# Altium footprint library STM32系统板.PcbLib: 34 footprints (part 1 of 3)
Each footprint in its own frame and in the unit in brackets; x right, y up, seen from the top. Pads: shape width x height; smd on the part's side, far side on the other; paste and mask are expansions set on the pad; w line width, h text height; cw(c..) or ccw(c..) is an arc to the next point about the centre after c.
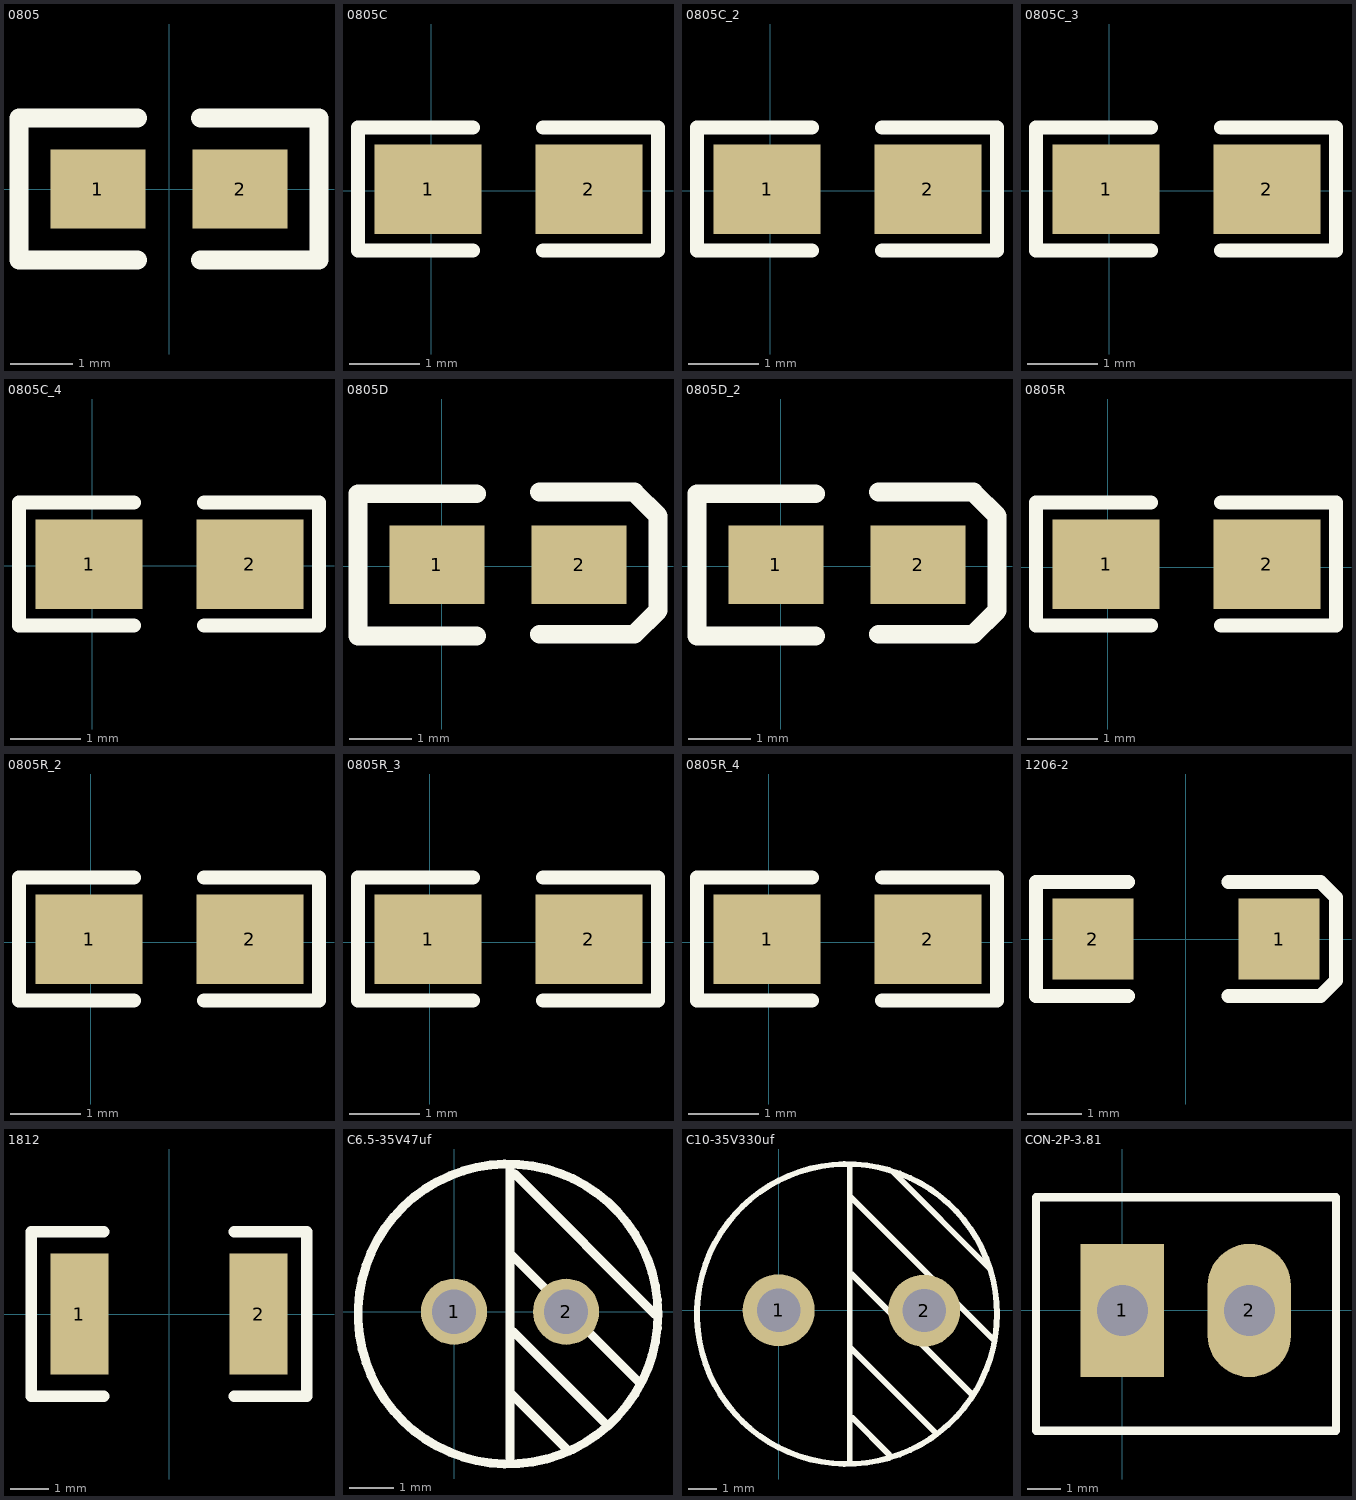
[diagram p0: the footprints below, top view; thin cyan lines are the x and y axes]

## 0805 [mil]
pads (2):
  rect 60x50 smd: 1(-45,0) 2(45,0)
Top Overlay:
  lines w12: -20,-45 -95,-45 -95,45 -20,45 ; 20,-45 95,-45 95,45 20,45

## 0805C [mil]
pads (2):
  rect 60x50 smd: 1(-1.89,0.71) 2(88.11,0.71)
Top Overlay:
  lines w7.87: 23.15,-33.54 -41.02,-33.54 -41.02,35.35 23.15,35.35 ; 62.52,-33.54 126.69,-33.54 126.69,35.35 62.52,35.35

## 0805C_2 [mil]
pads (2):
  rect 60x50 smd: 1(-1.89,0.71) 2(88.11,0.71)
Top Overlay:
  lines w7.87: 23.15,-33.54 -41.02,-33.54 -41.02,35.35 23.15,35.35 ; 62.52,-33.54 126.69,-33.54 126.69,35.35 62.52,35.35

## 0805C_3 [mil]
pads (2):
  rect 60x50 smd: 1(-1.89,0.71) 2(88.11,0.71)
Top Overlay:
  lines w7.87: 23.15,-33.54 -41.02,-33.54 -41.02,35.35 23.15,35.35 ; 62.52,-33.54 126.69,-33.54 126.69,35.35 62.52,35.35

## 0805C_4 [mil]
pads (2):
  rect 60x50 smd: 1(-1.89,0.71) 2(88.11,0.71)
Top Overlay:
  lines w7.87: 23.15,-33.54 -41.02,-33.54 -41.02,35.35 23.15,35.35 ; 62.52,-33.54 126.69,-33.54 126.69,35.35 62.52,35.35

## 0805D [mil]
pads (2):
  rect 60x50 smd: 1(-3.11,0.94) 2(86.89,0.94)
Top Overlay:
  lines w12: 21.89,-44.06 -53.11,-44.06 -53.11,45.94 21.89,45.94 ; 61.89,-43.07 121.89,-43.07 136.89,-28.07 136.89,31.93 121.89,46.93 61.89,46.93

## 0805D_2 [mil]
pads (2):
  rect 60x50 smd: 1(-3.11,0.94) 2(86.89,0.94)
Top Overlay:
  lines w12: 21.89,-44.06 -53.11,-44.06 -53.11,45.94 21.89,45.94 ; 61.89,-43.07 121.89,-43.07 136.89,-28.07 136.89,31.93 121.89,46.93 61.89,46.93

## 0805R [mil]
pads (2):
  rect 60x50 smd: 1(-0.91,1.69) 2(89.09,1.69)
Top Overlay:
  lines w7.87: 24.13,-32.56 -40.04,-32.56 -40.04,36.34 24.13,36.34 ; 63.5,-32.56 127.68,-32.56 127.68,36.34 63.5,36.34

## 0805R_2 [mil]
pads (2):
  rect 60x50 smd: 1(-0.91,1.69) 2(89.09,1.69)
Top Overlay:
  lines w7.87: 24.13,-32.56 -40.04,-32.56 -40.04,36.34 24.13,36.34 ; 63.5,-32.56 127.68,-32.56 127.68,36.34 63.5,36.34

## 0805R_3 [mil]
pads (2):
  rect 60x50 smd: 1(-0.91,1.69) 2(89.09,1.69)
Top Overlay:
  lines w7.87: 24.13,-32.56 -40.04,-32.56 -40.04,36.34 24.13,36.34 ; 63.5,-32.56 127.68,-32.56 127.68,36.34 63.5,36.34

## 0805R_4 [mil]
pads (2):
  rect 60x50 smd: 1(-0.91,1.69) 2(89.09,1.69)
Top Overlay:
  lines w7.87: 24.13,-32.56 -40.04,-32.56 -40.04,36.34 24.13,36.34 ; 63.5,-32.56 127.68,-32.56 127.68,36.34 63.5,36.34

## 1206-2 [mm]
pads (2):
  rect 1.5x1.5 smd: 1(1.714,0) 2(-1.714,0)
Top Overlay:
  lines w0.254: -1.064,-1.05 -2.764,-1.05 -2.764,0 -2.764,1.05 -1.064,1.05 ; 0.78,-1.05 2.48,-1.05 2.765,-0.766 2.765,0 2.765,0.766 2.48,1.05 0.78,1.05

## 1812 [mil]
pads (2):
  rect 60x125 smd: 1(-92.5,0) 2(92.5,0)
Top Overlay:
  lines w12: -67.5,-85 -142.5,-85 -142.5,85 -67.5,85 ; 67.5,-85 142.5,-85 142.5,85 67.5,85

## C6.5-35V47uf [mm]
pads (2):
  round 1.5 hole 1: 1(0,0) 2(2.54,0)
Top Overlay:
  circle w0.2: c1.223,-0.051 r3.4
  lines w0.2: 1.27,-3.302 1.27,3.251 ; 1.293,1.298 4.191,-1.6 ; 1.295,-1.854 2.603,-3.162 ; 1.346,-0.457 3.454,-2.565 ; 1.372,3.124 4.559,-0.064

## C10-35V330uf [mm]
pads (2):
  round 2.5 hole 1.5: 1(0,0) 2(5.044,-0.009)
Top Overlay:
  circle w0.2: c2.369,-0.127 r5.2
  lines w0.2: 2.464,-5.283 2.464,5.029 ; 2.489,-1.295 5.461,-4.267 ; 2.515,1.27 6.731,-2.946 ; 2.515,3.912 7.478,-1.056 ; 2.565,-3.734 3.835,-5.004 ; 3.962,4.801 7.328,1.435

## CON-2P-3.81 [mm]
pads (2):
  rect 2.5x4 hole 1.524: 1(0,0)
  oval 2.5x4 hole 1.524: 2(3.81,0)
Top Overlay:
  lines w0.254: -2.591,-3.607 6.409,-3.607 6.409,3.393 -2.591,3.393 -2.591,-3.607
